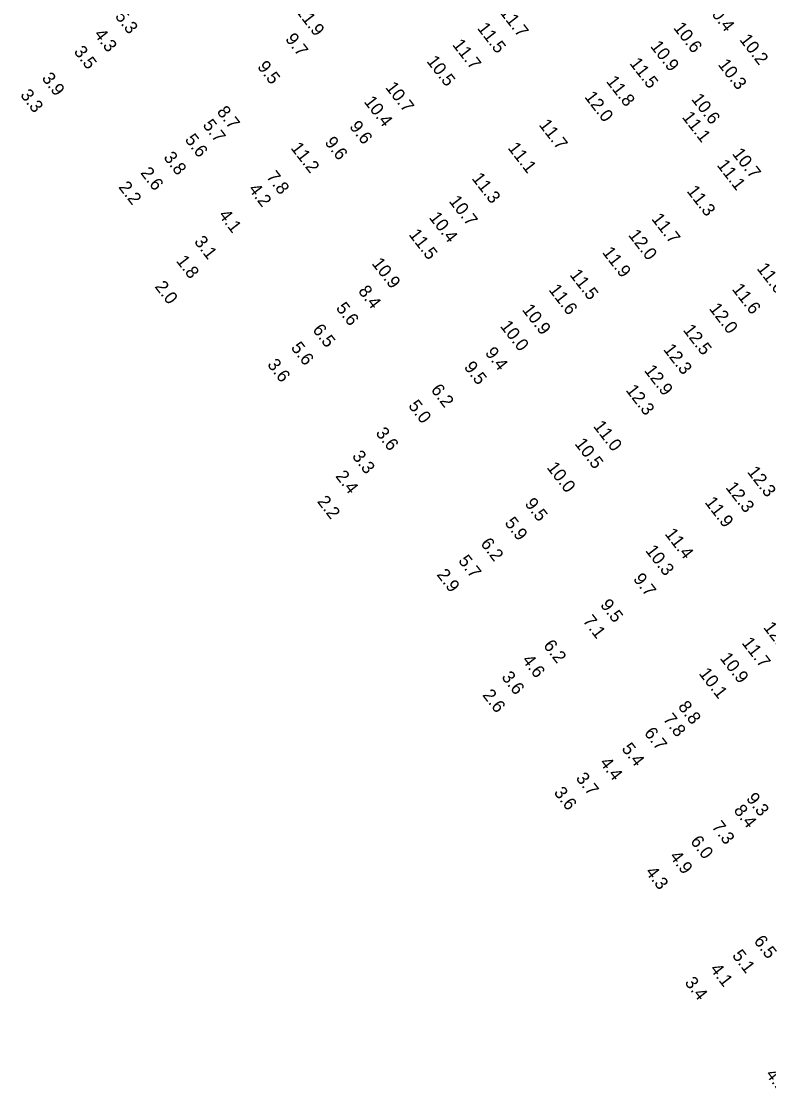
# Model space of a CAD drawing. Extents: x 815385 to 820851, y 582449 to 604245.
# Drawn here: x 819175 to 819468.3, y 593491.2 to 593911.8 of the extents above; entities that cross this region are included whole.
import ezdxf

# ---------------------------------------------------------------- set-up
doc = ezdxf.new("R2010")
doc.units = 0
for name, color, linetype in [('V-TOPO-SOUN-011609', 7, 'Continuous'), ('V-TOPO-SOUN-020509C', 7, 'Continuous'), ('V-TOPO-SOUN-112008', 7, 'Continuous'), ('V-TOPO-SOUN-EXCSS', 7, 'Continuous')]:
    doc.layers.add(name, color=color, linetype=linetype)

msp = doc.modelspace()

# ---------------------------------------------------------------- texts
at = {"layer": 'V-TOPO-SOUN-011609'}
for s, p in [('10.2 ', (819456.71, 593904.53)), ('10.3 ', (819448.24, 593894.78))]:
    msp.add_text(s, height=5, rotation=307.782, dxfattribs=at).set_placement(p)
at = {"layer": 'V-TOPO-SOUN-020509C'}
for s, p in [('5.3', (819211.55, 593913.73)), ('11.9 ', (819282.5, 593915.83)), ('11.7 ', (819362.58, 593915.28)), ('4.3', (819203.31, 593906.6)), ('11.5 ', (819353.74, 593909.05)), ('9.7', (819278.36, 593904.83)), ('11.7 ', (819343.99, 593902.56)), ('10.9 ', (819421.7, 593901.93)), ('3.5', (819195.37, 593899.85)), ('9.5', (819267.38, 593893.95)), ('10.5 ', (819333.86, 593896.08)), ('11.5 ', (819413.53, 593895.25)), ('3.9', (819182.8, 593889.39)), ('10.7 ', (819317.69, 593885.78)), ('11.8 ', (819404.36, 593888.16)), ('3.3', (819174.36, 593882.82)), ('12.0 ', (819395.84, 593882.08)), ('8.7', (819251.53, 593876.23)), ('10.4 ', (819309.25, 593880.21)), ('5.7', (819245.95, 593871)), ('9.6', (819303.57, 593870.42)), ('11.7 ', (819377.95, 593871.1)), ('5.6', (819238.95, 593865.28)), ('9.6', (819293.85, 593864.2)), ('11.2 ', (819280.5, 593862.04)), ('11.1 ', (819365.74, 593862.03)), ('10.7 ', (819453.82, 593859.77)), ('3.8', (819230.59, 593858.32)), ('11.1 ', (819447.82, 593855.27)), ('2.6', (819221.54, 593852.25)), ('7.8', (819270.95, 593850.7)), ('2.2', (819212.91, 593846.67)), ('11.3 ', (819351.59, 593850.09)), ('4.2', (819263.94, 593845.84)), ('11.3 ', (819435.99, 593845.1)), ('10.7 ', (819342.61, 593841.14)), ('4.1', (819252.22, 593835.65)), ('10.4 ', (819334.8, 593834.72)), ('11.7 ', (819422.14, 593834.19)), ('11.5 ', (819326.86, 593828.02)), ('12.0 ', (819413.04, 593827.83)), ('3.1', (819242.61, 593825.24)), ('1.8', (819235.56, 593817.66)), ('11.9 ', (819402.82, 593821.02)), ('10.9 ', (819312.33, 593816.69)), ('11.6 ', (819463.49, 593814.7)), ('11.5 ', (819390.02, 593812.21)), ('2.0', (819227.16, 593807.58)), ('8.4', (819307.01, 593805.81)), ('11.6 ', (819381.79, 593806.34)), ('11.6 ', (819453.74, 593806.6)), ('5.6', (819298.26, 593799.15)), ('10.9 ', (819371.35, 593798.51)), ('12.0 ', (819444.76, 593798.95)), ('10.0 ', (819362.71, 593792.08)), ('6.5', (819289.07, 593790.63)), ('12.5 ', (819434.52, 593790.55)), ('5.6', (819280.59, 593783.6)), ('9.4', (819356.8, 593781.59)), ('12.3 ', (819426.78, 593782.92)), ('3.6', (819271.32, 593776.97)), ('9.5', (819348.51, 593775.98)), ('12.9 ', (819419.27, 593774.66)), ('6.2', (819335.54, 593767.07)), ('12.3 ', (819412.05, 593766.93)), ('5.0', (819326.68, 593760.79)), ('3.6', (819313.86, 593750.09)), ('11.0 ', (819399.29, 593752.78)), ('10.5 ', (819391.99, 593745.9)), ('3.3', (819304.6, 593740.99)), ('2.4', (819298.08, 593733.18)), ('10.0 ', (819381.04, 593736.55)), ('12.3 ', (819459.73, 593734.83)), ('12.3 ', (819451.24, 593728.71)), ('2.2', (819290.9, 593723.24)), ('9.5', (819372.38, 593722.34)), ('11.9 ', (819443.06, 593722.89)), ('5.9', (819364.49, 593714.82)), ('11.4 ', (819427.37, 593710.5)), ('6.2', (819355.03, 593706.67)), ('10.3 ', (819419.75, 593703.95)), ('5.7', (819346.3, 593699.93)), ('2.9', (819337.85, 593694.5)), ('9.7', (819414.95, 593692.79)), ('9.5', (819402.02, 593682.63)), ('7.1', (819395.19, 593676.35)), ('6.2', (819379.69, 593666.67)), ('4.6', (819371.34, 593660.91)), ('3.6', (819363.26, 593654.29)), ('2.6', (819355.79, 593647.23))]:
    msp.add_text(s, height=5, rotation=307.782, dxfattribs=at).set_placement(p)
at = {"layer": 'V-TOPO-SOUN-112008'}
for s, p in [('12.5 ', (819466.05, 593673.79)), ('11.7 ', (819457.57, 593667.72)), ('10.9 ', (819448.99, 593661.71)), ('10.1 ', (819440.73, 593655.7)), ('8.8', (819432.55, 593642.66)), ('7.8', (819426.64, 593637.74)), ('6.7', (819419.26, 593632.33)), ('5.4', (819410.4, 593626.16)), ('4.4', (819401.82, 593620.61)), ('3.7', (819392.43, 593614.56)), ('3.6', (819383.81, 593608.93)), ('9.3', (819459.3, 593606.6)), ('8.4', (819454.41, 593601.96)), ('7.3', (819445.78, 593595.51)), ('6.0', (819437.4, 593589.77)), ('4.9', (819429.28, 593583.84)), ('4.3', (819419.76, 593577.74)), ('6.5', (819462.31, 593550.64)), ('5.1', (819453.81, 593544.97)), ('4.1', (819445.12, 593539.63)), ('3.4', (819435.17, 593534.33)), ('4.1', (819466.97, 593498.29))]:
    msp.add_text(s, height=5, rotation=307.782, dxfattribs=at).set_placement(p)
at = {"layer": 'V-TOPO-SOUN-EXCSS'}
for s, p in [('10.4 ', (819443.47, 593917.56)), ('10.6 ', (819430.73, 593909.2)), ('10.6 ', (819437.8, 593881.18)), ('11.1 ', (819434.14, 593874.13))]:
    msp.add_text(s, height=5, rotation=307.782, dxfattribs=at).set_placement(p)

doc.saveas('drawing.dxf')
